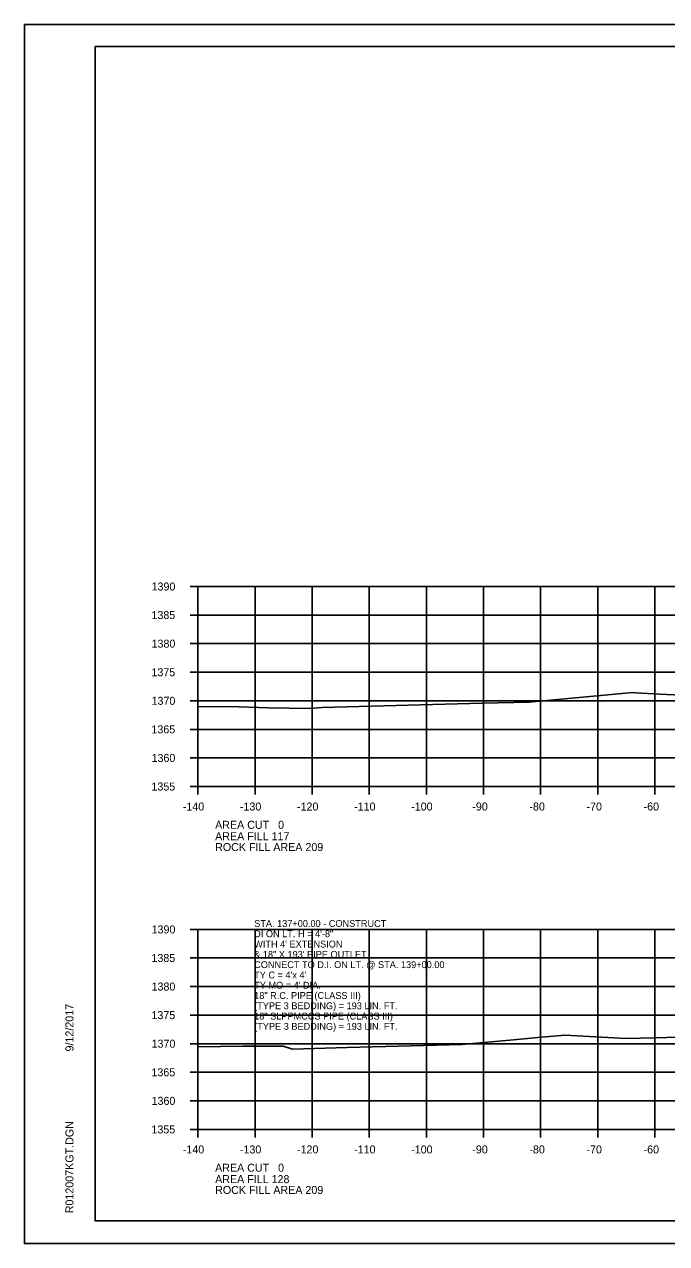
# Model space of a CAD drawing. Extents: x 1374311 to 1383814, y 384102 to 406278.
# Drawn here: x 1381458.2 to 1381570.7, y 388591.4 to 388804.7 of the extents above; entities that cross this region are included whole.
import ezdxf

# ---------------------------------------------------------------- set-up
doc = ezdxf.new("R2010")
doc.units = 0
for name, color, linetype in [('R_Axis', 7, 'Continuous'), ('R_Axis Annot', 7, 'Continuous'), ('R_Border', 7, 'Continuous'), ('R_Exist Surface', 7, 'Continuous'), ('R_Grid', 7, 'Continuous'), ('R_No Plot', 7, 'Continuous'), ('R_Water Annot', 7, 'Continuous')]:
    doc.layers.add(name, color=color, linetype=linetype)

msp = doc.modelspace()

# ---------------------------------------------------------------- linework, layer by layer
at = {"layer": 'R_Axis'}
for p, q in [((1381487.26, 388706.34), (1381488.66, 388706.34)), ((1381488.66, 388671.34), (1381488.66, 388706.34)), ((1381487.26, 388701.34), (1381488.66, 388701.34)), ((1381487.26, 388696.34), (1381488.66, 388696.34)), ((1381487.26, 388691.34), (1381488.66, 388691.34)), ((1381487.26, 388686.34), (1381488.66, 388686.34)), ((1381487.26, 388681.34), (1381488.66, 388681.34)), ((1381487.26, 388676.34), (1381488.66, 388676.34)), ((1381487.26, 388671.34), (1381488.66, 388671.34)), ((1381488.66, 388671.34), (1381768.66, 388671.34)), ((1381488.66, 388669.94), (1381488.66, 388671.34)), ((1381498.66, 388669.94), (1381498.66, 388671.34)), ((1381508.66, 388669.94), (1381508.66, 388671.34)), ((1381518.66, 388669.94), (1381518.66, 388671.34)), ((1381528.66, 388669.94), (1381528.66, 388671.34)), ((1381538.66, 388669.94), (1381538.66, 388671.34)), ((1381548.66, 388669.94), (1381548.66, 388671.34)), ((1381558.66, 388669.94), (1381558.66, 388671.34)), ((1381568.66, 388669.94), (1381568.66, 388671.34)), ((1381487.26, 388646.34), (1381488.66, 388646.34)), ((1381488.66, 388611.34), (1381488.66, 388646.34)), ((1381487.26, 388641.34), (1381488.66, 388641.34)), ((1381487.26, 388636.34), (1381488.66, 388636.34)), ((1381487.26, 388631.34), (1381488.66, 388631.34)), ((1381487.26, 388626.34), (1381488.66, 388626.34)), ((1381487.26, 388621.34), (1381488.66, 388621.34)), ((1381487.26, 388616.34), (1381488.66, 388616.34)), ((1381487.26, 388611.34), (1381488.66, 388611.34)), ((1381488.66, 388611.34), (1381768.66, 388611.34)), ((1381488.66, 388609.94), (1381488.66, 388611.34)), ((1381498.66, 388609.94), (1381498.66, 388611.34)), ((1381508.66, 388609.94), (1381508.66, 388611.34)), ((1381518.66, 388609.94), (1381518.66, 388611.34)), ((1381528.66, 388609.94), (1381528.66, 388611.34)), ((1381538.66, 388609.94), (1381538.66, 388611.34)), ((1381548.66, 388609.94), (1381548.66, 388611.34)), ((1381558.66, 388609.94), (1381558.66, 388611.34)), ((1381568.66, 388609.94), (1381568.66, 388611.34))]:
    msp.add_line(p, q, dxfattribs=at)
at = {"layer": 'R_Border'}
for p, q in [((1381470.66, 388800.8), (1381786.84, 388800.8)), ((1381470.66, 388595.34), (1381470.66, 388800.8)), ((1381470.66, 388595.34), (1381470.66, 388595.34)), ((1381786.84, 388595.34), (1381470.66, 388595.34))]:
    msp.add_line(p, q, dxfattribs=at)
at = {"layer": 'R_Exist Surface'}
for points in [[(1381488.66, 388685.31), (1381494.04, 388685.37), (1381501.02, 388685.08), (1381508.24, 388684.98), (1381509.69, 388685.11), (1381510.39, 388685.18), (1381538.44, 388685.91), (1381546.71, 388686.12), (1381547.27, 388686.17), (1381564.8, 388687.78), (1381565.26, 388687.75), (1381569.55, 388687.52), (1381575.77, 388687.2)], [(1381488.66, 388625.79), (1381496.59, 388625.89), (1381503.58, 388625.89), (1381505.2, 388625.4), (1381514.79, 388625.65), (1381534.87, 388626.19), (1381543.3, 388626.95), (1381548.83, 388627.46), (1381552.95, 388627.82), (1381561.49, 388627.38), (1381563.64, 388627.26), (1381566.18, 388627.32), (1381575.44, 388627.55)]]:
    msp.add_lwpolyline(points, dxfattribs=at)
at = {"layer": 'R_Grid'}
for p, q in [((1381488.66, 388706.34), (1381768.66, 388706.34)), ((1381488.66, 388671.34), (1381488.66, 388706.34)), ((1381498.66, 388671.34), (1381498.66, 388706.34)), ((1381508.66, 388671.34), (1381508.66, 388706.34)), ((1381518.66, 388671.34), (1381518.66, 388706.34)), ((1381528.66, 388671.34), (1381528.66, 388706.34)), ((1381538.66, 388671.34), (1381538.66, 388706.34)), ((1381548.66, 388671.34), (1381548.66, 388706.34)), ((1381558.66, 388671.34), (1381558.66, 388706.34)), ((1381568.66, 388671.34), (1381568.66, 388706.34)), ((1381488.66, 388701.34), (1381768.66, 388701.34)), ((1381488.66, 388696.34), (1381768.66, 388696.34)), ((1381488.66, 388691.34), (1381768.66, 388691.34)), ((1381488.66, 388686.34), (1381768.66, 388686.34)), ((1381488.66, 388681.34), (1381768.66, 388681.34)), ((1381488.66, 388676.34), (1381768.66, 388676.34)), ((1381488.66, 388671.34), (1381768.66, 388671.34)), ((1381488.66, 388646.34), (1381768.66, 388646.34)), ((1381488.66, 388611.34), (1381488.66, 388646.34)), ((1381498.66, 388611.34), (1381498.66, 388646.34)), ((1381508.66, 388611.34), (1381508.66, 388646.34)), ((1381518.66, 388611.34), (1381518.66, 388646.34)), ((1381528.66, 388611.34), (1381528.66, 388646.34)), ((1381538.66, 388611.34), (1381538.66, 388646.34)), ((1381548.66, 388611.34), (1381548.66, 388646.34)), ((1381558.66, 388611.34), (1381558.66, 388646.34)), ((1381568.66, 388611.34), (1381568.66, 388646.34)), ((1381488.66, 388641.34), (1381768.66, 388641.34)), ((1381488.66, 388636.34), (1381768.66, 388636.34)), ((1381488.66, 388631.34), (1381768.66, 388631.34)), ((1381488.66, 388626.34), (1381768.66, 388626.34)), ((1381488.66, 388621.34), (1381768.66, 388621.34)), ((1381488.66, 388616.34), (1381768.66, 388616.34)), ((1381488.66, 388611.34), (1381768.66, 388611.34))]:
    msp.add_line(p, q, dxfattribs=at)
at = {"layer": 'R_No Plot'}
for p, q in [((1381458.26, 388804.7), (1381791.59, 388804.7)), ((1381458.26, 388591.36), (1381791.59, 388591.36))]:
    msp.add_line(p, q, dxfattribs=at)
for points in [[(1381458.25, 388804.7), (1381791.59, 388804.7), (1381791.59, 388591.36), (1381458.25, 388591.36)], [(1381704.58, 388800.8), (1381704.58, 388790.92), (1381740.31, 388790.92), (1381740.31, 388788), (1381763.51, 388788), (1381763.51, 388764.79), (1381786.84, 388764.79), (1381786.84, 388595.34), (1381470.66, 388595.34), (1381470.66, 388800.8)]]:
    msp.add_lwpolyline(points, close=True, dxfattribs=at)

# ---------------------------------------------------------------- texts
at = {"layer": 'R_Axis Annot'}
for s, p in [('1390', (1381480.53, 388705.64)), ('1385', (1381480.51, 388700.64)), ('1380', (1381480.53, 388695.64)), ('1375', (1381480.51, 388690.64)), ('1370', (1381480.53, 388685.64)), ('1365', (1381480.51, 388680.64)), ('1360', (1381480.53, 388675.64)), ('1355', (1381480.51, 388670.64)), ('-140', (1381486, 388667.14)), ('-130', (1381496, 388667.14)), ('-120', (1381506, 388667.14)), ('-110', (1381516, 388667.14)), ('-100', (1381526, 388667.14)), ('-90', (1381536.7, 388667.14)), ('-80', (1381546.7, 388667.14)), ('-70', (1381556.7, 388667.14)), ('-60', (1381566.7, 388667.14)), ('AREA CUT   0', (1381491.66, 388663.94)), ('AREA FILL 117', (1381491.66, 388661.94)), ('ROCK FILL AREA 209', (1381491.66, 388660.05)), ('1390', (1381480.53, 388645.64)), ('1385', (1381480.51, 388640.64)), ('1380', (1381480.53, 388635.64)), ('1375', (1381480.51, 388630.64)), ('1370', (1381480.53, 388625.64)), ('1365', (1381480.51, 388620.64)), ('1360', (1381480.53, 388615.64)), ('1355', (1381480.51, 388610.64)), ('-140', (1381486, 388607.14)), ('-130', (1381496, 388607.14)), ('-120', (1381506, 388607.14)), ('-110', (1381516, 388607.14)), ('-100', (1381526, 388607.14)), ('-90', (1381536.7, 388607.14)), ('-80', (1381546.7, 388607.14)), ('-70', (1381556.7, 388607.14)), ('-60', (1381566.7, 388607.14)), ('AREA CUT   0', (1381491.66, 388603.94)), ('AREA FILL 128', (1381491.66, 388601.94)), ('ROCK FILL AREA 209', (1381491.66, 388600.05))]:
    msp.add_text(s, height=1.4, dxfattribs=at).set_placement(p)
at = {"layer": 'R_Border'}
for s, p in [('9/12/2017', (1381466.85, 388624.98)), ('R012007KGT.DGN', (1381466.85, 388596.67))]:
    msp.add_text(s, height=1.4, rotation=90, dxfattribs=at).set_placement(p)
at = {"layer": 'R_Water Annot'}
for s, p in [('STA. 137+00.00 - CONSTRUCT', (1381498.5, 388646.77)), ('DI ON LT. H = 4\'-8"', (1381498.5, 388644.97)), ("WITH 4' EXTENSION ", (1381498.5, 388643.17)), ('& 18" X 193\' PIPE OUTLET', (1381498.5, 388641.37)), ('CONNECT TO D.I. ON LT. @ STA. 139+00.00', (1381498.5, 388639.57)), ("TY C = 4'x 4'", (1381498.5, 388637.77)), ("TY MO = 4' DIA.", (1381498.5, 388635.97)), ('18" R.C. PIPE (CLASS III)', (1381498.5, 388634.17)), ('(TYPE 3 BEDDING) = 193 LIN. FT.', (1381498.5, 388632.37)), ('18" SLPPMCCS PIPE (CLASS III)', (1381498.5, 388630.57)), ('(TYPE 3 BEDDING) = 193 LIN. FT.', (1381498.5, 388628.77))]:
    msp.add_text(s, height=1.2, dxfattribs=at).set_placement(p)

doc.saveas('drawing.dxf')
